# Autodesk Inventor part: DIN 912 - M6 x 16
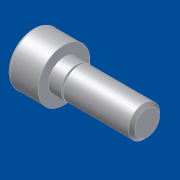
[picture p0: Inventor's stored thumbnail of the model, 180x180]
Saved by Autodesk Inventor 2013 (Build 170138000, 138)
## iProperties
Created: 2001-08
Part Number: DIN 912 - M6 x 16
Material: Standard
Catalog Web Link: http://www.redspark.com/catalogs/din/de/index.htm?doNavigateId=32E941FC-C430-11D4-A9F1-0080AD303E0A|0557D50DB16611D4BA6900C04F798F98|true
Description: Zylinderschraube
Document SubType Name: Standard Catalog Part
Standard: DIN 912 - M6 x 16
Designer: dl
Density: 1 g/cm^3
Control State: 0
Master: False
Checked Out: False
Shininess: 20.0
Length Units: 11269
Angle Units: 11279
Time Units: 11290
Mass Units: 11283
Length Display Precision: 3
Angle Display Precision: 2
CLASSIFICATION: 31161501 un/spsc
MANUFACTURER: DIN Standardsystem
Density: 0.0
Volumn: 0.0
Area: 0.0
PropertySet Name: Model Information
Author: dl
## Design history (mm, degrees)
feature "Basis1"
body "Solid1"
